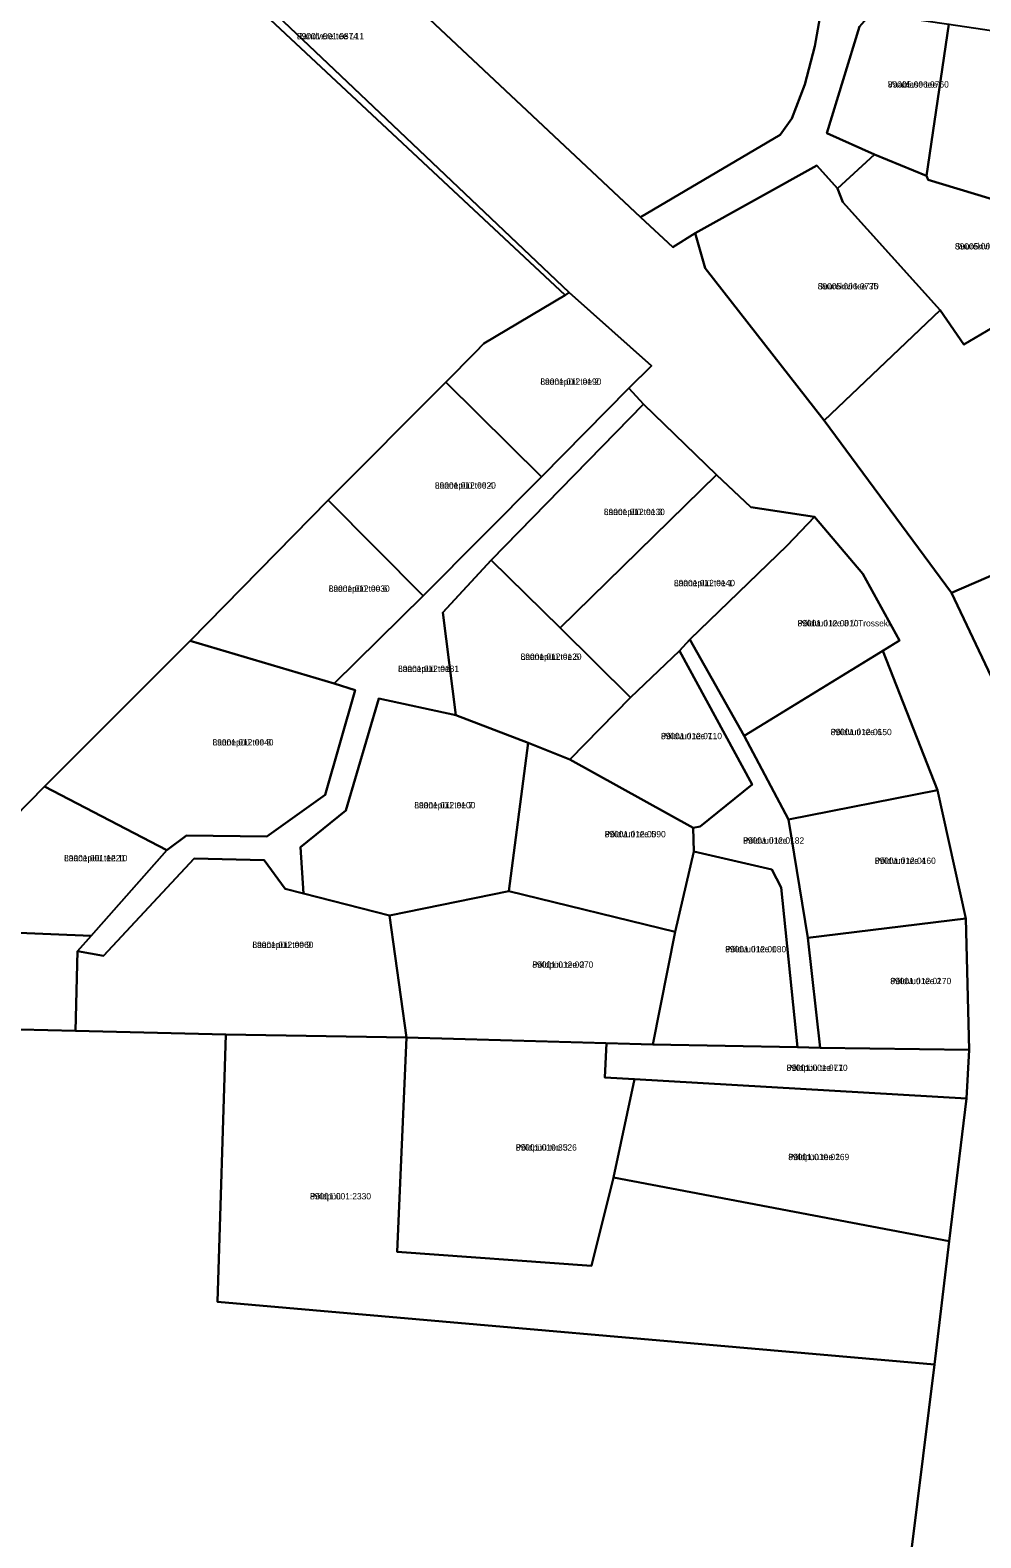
# Model space of a CAD drawing. Extents: x 526849 to 562296, y 6591741 to 6618546.
# Drawn here: x 551112.7 to 551338.6, y 6597308.8 to 6597667.2 of the extents above; entities that cross this region are included whole.
import ezdxf

# ---------------------------------------------------------------- set-up
doc = ezdxf.new("R2010")
doc.units = 0
for name, color, linetype in [('L_AADRESS', 7, 'Continuous'), ('PIIR', 7, 'Continuous'), ('TUNNUS', 7, 'Continuous')]:
    doc.layers.add(name, color=color, linetype=linetype)

msp = doc.modelspace()

# ---------------------------------------------------------------- linework, layer by layer
at = {"layer": 'PIIR'}
for points in [[(550642.16, 6598609.49), (550659.82, 6598605.14), (550668.05, 6598592.24), (550686.56, 6598557.97), (551117.21, 6597760.6), (551147.24, 6597726.55), (551257.76, 6597622.75), (551265.4, 6597615.62), (551270.73, 6597618.95), (551273.1, 6597610.57), (551301.36, 6597574.38), (551331.62, 6597533.44), (551350.49, 6597493.63), (551353.55, 6597467.1), (551357.58, 6597431.51), (551357.52, 6597425.22), (551353.03, 6597392.12), (551349.26, 6597364.37), (551348.43, 6597356.79), (551345.28, 6597327.37), (551348.98, 6597326.82), (551346.35, 6597305.43)], [(550654.47, 6598566.22), (551067.88, 6597797.51), (551097.17, 6597747.35), (551112.99, 6597725.8), (551163.71, 6597675.41), (551239.83, 6597604.2), (551220.5, 6597592.7), (551218.4, 6597590.52), (551211.44, 6597583.52), (551183.52, 6597555.45), (551150.71, 6597522.01), (551116.04, 6597487.35), (551083.02, 6597453.74), (551063.31, 6597433.76), (550996.93, 6597374.7), (551000.17, 6597366.58), (550882.12, 6597247.71)], [(551305.84, 6597174.43), (551327.65, 6597350), (551331.12, 6597379.31), (551335.26, 6597413.22), (551335.82, 6597424.77), (551335.05, 6597456.03), (551328.33, 6597486.55), (551315.33, 6597519.65), (551319.3, 6597522.09), (551310.55, 6597537.93), (551299.09, 6597551.47), (551283.92, 6597553.75), (551275.78, 6597561.5), (551258.47, 6597578.25), (551254.96, 6597582.07), (551260.37, 6597587.39), (551240.78, 6597604.79), (551186.49, 6597656.31), (551132.15, 6597707.86), (551112.99, 6597725.8), (551097.17, 6597747.35), (550654.47, 6598566.22)], [(551300.83, 6597672.8), (551299.16, 6597663.39), (551296.79, 6597654.29), (551293.69, 6597646.18), (551290.97, 6597642.31), (551257.76, 6597622.75), (551147.24, 6597726.55)], [(551309.76, 6597668.02), (551302.04, 6597642.71), (551313.34, 6597637.65), (551304.57, 6597629.5), (551299.67, 6597634.96), (551270.73, 6597618.95), (551265.4, 6597615.62), (551257.76, 6597622.75), (551290.97, 6597642.31), (551293.69, 6597646.18), (551296.79, 6597654.29), (551299.16, 6597663.39), (551300.83, 6597672.8)], [(551342.79, 6597538.24), (551331.62, 6597533.44), (551301.36, 6597574.38), (551328.96, 6597600.64), (551334.57, 6597592.44), (551344.03, 6597598.02)]]:
    msp.add_lwpolyline(points, dxfattribs=at)
for points in [[(551163.71, 6597675.41), (551112.99, 6597725.8), (551132.15, 6597707.86), (551186.49, 6597656.31), (551240.78, 6597604.79), (551239.83, 6597604.2)], [(551302.04, 6597642.71), (551309.76, 6597668.02), (551312.01, 6597670.57), (551314.07, 6597671.07), (551330.99, 6597668.6), (551325.71, 6597632.51), (551313.34, 6597637.65)], [(551325.71, 6597632.51), (551330.99, 6597668.6), (551357.16, 6597664.73), (551356.92, 6597663), (551351.54, 6597623.87), (551326.14, 6597631.61)], [(551270.73, 6597618.95), (551299.67, 6597634.96), (551304.57, 6597629.5), (551305.83, 6597626.29), (551328.96, 6597600.64), (551301.36, 6597574.38), (551273.1, 6597610.57)], [(551305.83, 6597626.29), (551304.57, 6597629.5), (551313.34, 6597637.65), (551325.71, 6597632.51), (551326.14, 6597631.61), (551351.54, 6597623.87), (551344.03, 6597598.02), (551334.57, 6597592.44), (551328.96, 6597600.64)], [(551211.44, 6597583.52), (551218.4, 6597590.52), (551220.5, 6597592.7), (551239.83, 6597604.2), (551240.78, 6597604.79), (551260.37, 6597587.39), (551254.96, 6597582.07), (551234.19, 6597560.97)], [(551187.66, 6597481.7), (551176.94, 6597472.95), (551177.62, 6597461.97), (551173.29, 6597463.03), (551168.31, 6597469.9), (551151.68, 6597470.3), (551130.1, 6597447.16), (551123.94, 6597448.24), (551127.15, 6597451.89), (551145.15, 6597472.27), (551149.8, 6597475.77), (551168.91, 6597475.48), (551182.8, 6597485.39), (551189.94, 6597510.28), (551184.89, 6597511.9), (551206.07, 6597532.67), (551234.19, 6597560.97), (551254.96, 6597582.07), (551258.47, 6597578.25), (551222.25, 6597541.2), (551210.72, 6597528.78), (551213.85, 6597504.31), (551195.52, 6597508.31)], [(551183.52, 6597555.45), (551211.44, 6597583.52), (551234.19, 6597560.97), (551206.07, 6597532.67)], [(551222.25, 6597541.2), (551258.47, 6597578.25), (551275.78, 6597561.5), (551238.67, 6597525.07)], [(551238.67, 6597525.07), (551275.78, 6597561.5), (551283.92, 6597553.75), (551299.09, 6597551.47), (551292.63, 6597544.65), (551269.43, 6597522.32), (551267, 6597519.63), (551255.36, 6597508.5)], [(551183.52, 6597555.45), (551206.07, 6597532.67), (551184.89, 6597511.9), (551150.71, 6597522.01)], [(551282.38, 6597499.41), (551269.43, 6597522.32), (551292.63, 6597544.65), (551299.09, 6597551.47), (551310.55, 6597537.93), (551319.3, 6597522.09)], [(551210.72, 6597528.78), (551222.25, 6597541.2), (551238.67, 6597525.07), (551255.36, 6597508.5), (551240.94, 6597493.78), (551231.01, 6597497.76), (551213.85, 6597504.31)], [(551350.49, 6597493.63), (551331.62, 6597533.44), (551342.79, 6597538.24), (551346.69, 6597534.7), (551355.94, 6597510.14), (551374.5, 6597502.05), (551396.12, 6597500.57), (551392.38, 6597464.36), (551353.55, 6597467.1)], [(551145.15, 6597472.27), (551116.04, 6597487.35), (551150.71, 6597522.01), (551184.89, 6597511.9), (551189.94, 6597510.28), (551182.8, 6597485.39), (551168.91, 6597475.48), (551149.8, 6597475.77)], [(551270.28, 6597477.59), (551271.88, 6597477.88), (551284.26, 6597487.83), (551267, 6597519.63), (551269.43, 6597522.32), (551282.38, 6597499.41), (551292.93, 6597479.54), (551297.51, 6597451.43), (551300.47, 6597425.25), (551295.07, 6597425.4), (551291.18, 6597463.4), (551288.92, 6597467.67), (551270.44, 6597471.92)], [(551255.36, 6597508.5), (551267, 6597519.63), (551284.26, 6597487.83), (551271.88, 6597477.88), (551270.28, 6597477.59), (551240.94, 6597493.78)], [(551282.38, 6597499.41), (551315.33, 6597519.65), (551328.33, 6597486.55), (551292.93, 6597479.54)], [(551177.62, 6597461.97), (551176.94, 6597472.95), (551187.66, 6597481.7), (551195.52, 6597508.31), (551213.85, 6597504.31), (551231.01, 6597497.76), (551226.47, 6597462.54), (551198.06, 6597456.71)], [(551231.01, 6597497.76), (551240.94, 6597493.78), (551270.28, 6597477.59), (551270.44, 6597471.92), (551265.96, 6597452.84), (551226.47, 6597462.54)], [(551083.02, 6597453.74), (551116.04, 6597487.35), (551145.15, 6597472.27), (551127.15, 6597451.89)], [(551292.93, 6597479.54), (551328.33, 6597486.55), (551335.05, 6597456.03), (551297.51, 6597451.43)], [(551123.94, 6597448.24), (551130.1, 6597447.16), (551151.68, 6597470.3), (551168.31, 6597469.9), (551173.29, 6597463.03), (551177.62, 6597461.97), (551198.06, 6597456.71), (551202.08, 6597427.72), (551159.19, 6597428.46), (551123.43, 6597429.32)], [(551265.96, 6597452.84), (551270.44, 6597471.92), (551288.92, 6597467.67), (551291.18, 6597463.4), (551295.07, 6597425.4), (551260.64, 6597426.03)], [(551198.06, 6597456.71), (551226.47, 6597462.54), (551265.96, 6597452.84), (551260.64, 6597426.03), (551202.08, 6597427.72)], [(551297.51, 6597451.43), (551335.05, 6597456.03), (551335.82, 6597424.77), (551300.47, 6597425.25)], [(551063.31, 6597433.76), (551083.02, 6597453.74), (551127.15, 6597451.89), (551123.94, 6597448.24), (551123.43, 6597429.32), (551064.19, 6597430.76)], [(551159.19, 6597428.46), (551157.19, 6597364.86), (551327.65, 6597350), (551305.84, 6597174.43), (551262.18, 6597182.11), (551222.76, 6597188.93), (551183.34, 6597195.81), (551144.01, 6597202.58), (551128.73, 6597205.23), (551107.45, 6597232.01), (551098.85, 6597242.74), (551066.35, 6597283.61), (551064.54, 6597285.86), (551062.92, 6597287.79), (551000.17, 6597366.58), (550996.93, 6597374.7), (551063.31, 6597433.76), (551064.19, 6597430.76), (551123.43, 6597429.32)], [(551157.19, 6597364.86), (551159.19, 6597428.46), (551202.08, 6597427.72), (551199.86, 6597376.75), (551246.05, 6597373.42), (551251.35, 6597394.46), (551331.12, 6597379.31), (551327.65, 6597350)], [(551202.08, 6597427.72), (551249.67, 6597426.34), (551249.26, 6597418.25), (551256.31, 6597417.84), (551251.35, 6597394.46), (551246.05, 6597373.42), (551199.86, 6597376.75)], [(551335.82, 6597424.77), (551335.26, 6597413.22), (551256.31, 6597417.84), (551249.26, 6597418.25), (551249.67, 6597426.34), (551260.64, 6597426.03), (551295.07, 6597425.4), (551300.47, 6597425.25)], [(551335.26, 6597413.22), (551331.12, 6597379.31), (551251.35, 6597394.46), (551256.31, 6597417.84)]]:
    msp.add_lwpolyline(points, close=True, dxfattribs=at)

# ---------------------------------------------------------------- texts
at = {"layer": 'L_AADRESS'}
for s, p in [('Randvere tee L11', (551176.08, 6597665)), ('Vaablase tee 6', (551316.52, 6597653.52)), ('Suurekivi tee 33', (551332.47, 6597615.04)), ('Suurekivi tee 35', (551299.84, 6597605.54)), ('Laanepüü tee 2', (551233.93, 6597582.88)), ('Laanepüü tee 4', (551208.86, 6597558.2)), ('Laanepüü tee 3', (551249.02, 6597551.9)), ('Laanepüü tee 6', (551183.62, 6597533.67)), ('Laanepüü tee 1', (551265.69, 6597535)), ('Põldvuti tee 8 // Trosseki', (551295.06, 6597525.44)), ('Laanepüü tee 5', (551229.23, 6597517.49)), ('Laanepüü tee', (551200.1, 6597514.62)), ('Laanepüü tee 8', (551156, 6597497.14)), ('Põldvuti tee 7', (551262.6, 6597498.63)), ('Põldvuti tee 6', (551302.94, 6597499.59)), ('Laanepüü tee 7', (551203.97, 6597482.19)), ('Põldvuti tee 5', (551249.23, 6597475.3)), ('Põldvuti tee', (551282.13, 6597473.79)), ('Laanepüü tee 10', (551120.72, 6597469.62)), ('Põldvuti tee 4', (551313.42, 6597468.99)), ('Laanepüü tee 9', (551165.48, 6597449.01)), ('Põldvuti tee 1', (551277.86, 6597447.96)), ('Põldpüü tee 2', (551232.02, 6597444.29)), ('Põldvuti tee 2', (551317.1, 6597440.4)), ('Põldpüü tee L1', (551292.46, 6597419.78)), ('Põldpüü tee 3', (551228.09, 6597400.84)), ('Põldpüü tee 1', (551292.85, 6597398.57)), ('Põldpüü', (551179.18, 6597389.23))]:
    msp.add_text(s, height=1.5, dxfattribs=at).set_placement(p)
at = {"layer": 'TUNNUS'}
for s, p in [('89001:001:0874', (551176.08, 6597665)), ('89005:006:0760', (551316.52, 6597653.52)), ('89005:006:0730', (551332.47, 6597615.04)), ('89005:006:0770', (551299.84, 6597605.54)), ('89001:012:0190', (551233.93, 6597582.88)), ('89001:012:0020', (551208.86, 6597558.2)), ('89001:012:0130', (551249.02, 6597551.9)), ('89001:012:0030', (551183.62, 6597533.67)), ('89001:012:0140', (551265.69, 6597535)), ('89001:012:0010', (551295.06, 6597525.44)), ('89001:012:0120', (551229.23, 6597517.49)), ('89001:012:0181', (551200.1, 6597514.62)), ('89001:012:0040', (551156, 6597497.14)), ('89001:012:0110', (551262.6, 6597498.63)), ('89001:012:0150', (551302.94, 6597499.59)), ('89001:012:0100', (551203.97, 6597482.19)), ('89001:012:0090', (551249.23, 6597475.3)), ('89001:012:0182', (551282.13, 6597473.79)), ('89001:001:1221', (551120.72, 6597469.62)), ('89001:012:0160', (551313.42, 6597468.99)), ('89001:012:0060', (551165.48, 6597449.01)), ('89001:012:0080', (551277.86, 6597447.96)), ('89001:012:0070', (551232.02, 6597444.29)), ('89001:012:0170', (551317.1, 6597440.4)), ('89001:001:0770', (551292.46, 6597419.78)), ('89001:010:3526', (551228.09, 6597400.84)), ('89001:010:0269', (551292.85, 6597398.57)), ('89001:001:2330', (551179.18, 6597389.23))]:
    msp.add_text(s, height=1.5, dxfattribs=at).set_placement(p)

doc.saveas('drawing.dxf')
